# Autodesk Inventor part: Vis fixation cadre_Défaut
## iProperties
Shininess: 64.0
Length Units: 11269
Angle Units: 11279
Time Units: 11290
Mass Units: 11283
Length Display Precision: 3
Angle Display Precision: 2
Compacted: True
Part Number: Vis fixation cadre_Défaut
Document SubType Name: Modeling
Created: 2006-01
Material: Par défaut
Designer: Fricot
Density: 0.0
Volumn: 0.0
Area: 0.0
PropertySet Name: Model Information
Control State: 0
Master: False
Checked Out: False
Author: Fricot
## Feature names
1. Base1
